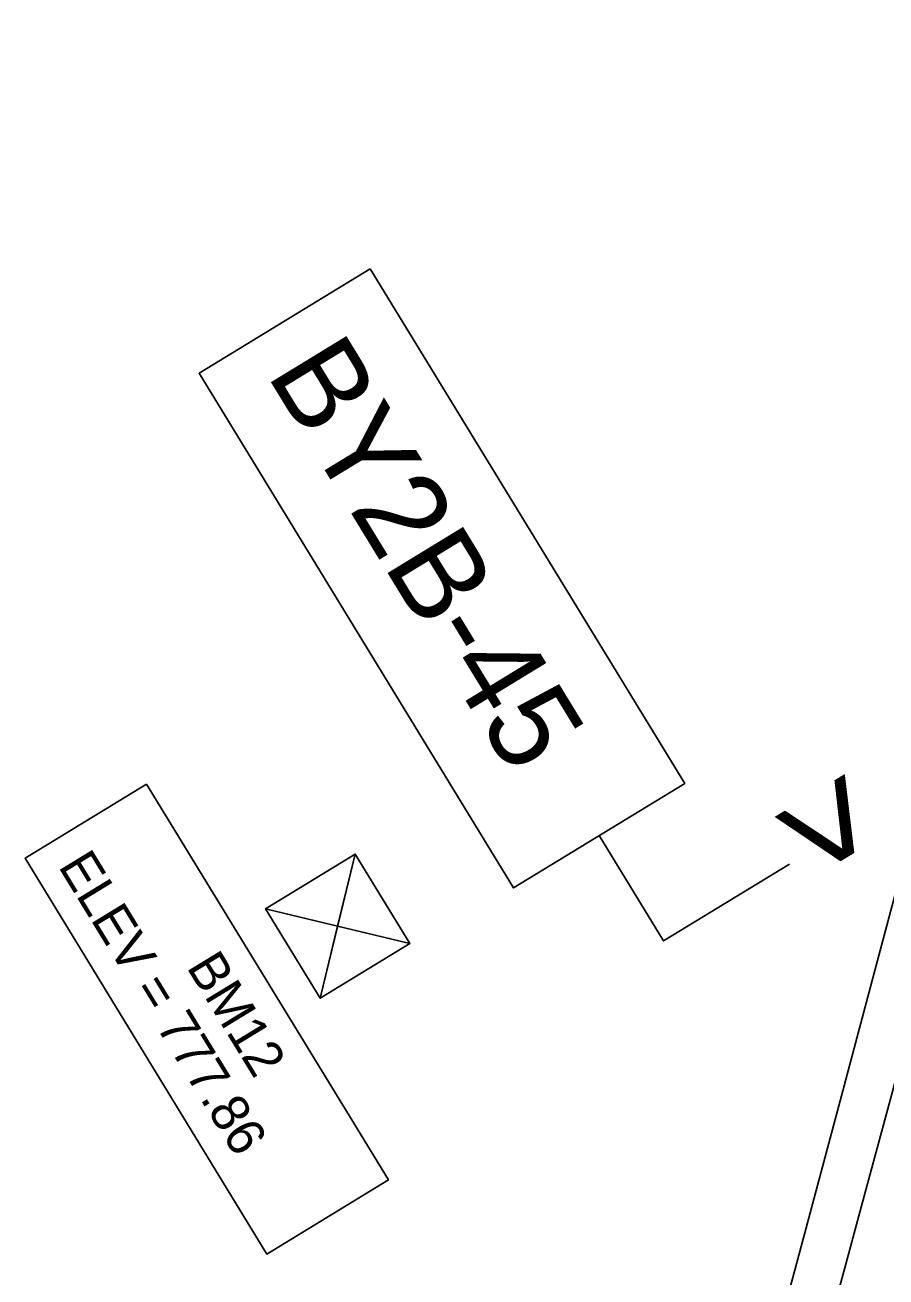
# Model space of a CAD drawing. Extents: x 1771071 to 1790027, y 804210 to 823391.
# Drawn here: x 1782718 to 1783081, y 815470 to 815999 of the extents above; entities that cross this region are included whole.
import ezdxf

# ---------------------------------------------------------------- set-up
doc = ezdxf.new("R2010")
doc.units = 0
for name, color, linetype in [('Default', 7, 'Continuous'), ('Exist Roads EOP', 7, 'Continuous'), ('Old_Level_57', 7, 'Continuous'), ('Proposed Right of Way Monument PSD Text', 7, 'Continuous')]:
    doc.layers.add(name, color=color, linetype=linetype)

msp = doc.modelspace()

# ---------------------------------------------------------------- linework, layer by layer
at = {"layer": 'Default'}
for points in [[(1782863.62, 815895.76), (1782996.28, 815678.64), (1782924.16, 815634.57), (1782791.5, 815851.69)], [(1782769.32, 815678.33), (1782871.32, 815511.4), (1782820.12, 815480.12), (1782718.12, 815647.05)]]:
    msp.add_lwpolyline(points, close=True, dxfattribs=at)
msp.add_lwpolyline([(1783040.44, 815644.52), (1782987.36, 815612.19), (1782960.23, 815656.61)], dxfattribs=at)
at = {"layer": 'Exist Roads EOP'}
for points in [[(1782983.08, 815250.42), (1782997.87, 815306.06), (1783014.55, 815368.48), (1783029.99, 815425.98), (1783044.8, 815481.13), (1783061.8, 815544.76), (1783077.09, 815601.83), (1783092.82, 815660.85), (1783108.2, 815717.8), (1783115.67, 815745.77), (1783122.14, 815769.94), (1783138.05, 815829.01), (1783153.26, 815886.72), (1783168.1, 815943.43), (1783182.63, 815998.55)], [(1783009.61, 815271.62), (1783016.48, 815296.9), (1783027.5, 815338.76), (1783039.98, 815385.98), (1783052.19, 815431.56), (1783063.75, 815474.24), (1783071.06, 815501.47), (1783083.34, 815546.57), (1783095.6, 815592.71), (1783103.23, 815621.01)]]:
    msp.add_lwpolyline(points, dxfattribs=at)
at = {"layer": 'Old_Level_57'}
for p, q in [((1782842.6, 815588.02), (1782857.28, 815648.82)), ((1782880.34, 815611.08), (1782819.54, 815625.76))]:
    msp.add_line(p, q, dxfattribs=at)
msp.add_lwpolyline([(1782857.28, 815648.82), (1782819.54, 815625.76), (1782842.6, 815588.02), (1782880.34, 815611.08)], close=True, dxfattribs=at)
for points in [[(1782849.94, 815618.42), (1782857.28, 815648.82), (1782819.54, 815625.76), (1782849.94, 815618.42)], [(1782849.94, 815618.42), (1782842.6, 815588.02), (1782880.34, 815611.08), (1782849.94, 815618.42)]]:
    msp.add_lwpolyline(points, dxfattribs=at)

# ---------------------------------------------------------------- texts
msp.add_text('>', height=46.95, rotation=301.4392, dxfattribs=at).set_placement((1783028.23, 815664.5))
at = {"layer": 'Proposed Right of Way Monument PSD Text'}
for s, height, p in [('BY2B-45', 37.325, (1782819.66, 815851.38)), ('ELEV = 777.86', 16, (1782731.87, 815643.73)), ('BM12', 16, (1782785.98, 815601.2))]:
    msp.add_text(s, height=height, rotation=301.4249, dxfattribs=at).set_placement(p)

doc.saveas('drawing.dxf')
